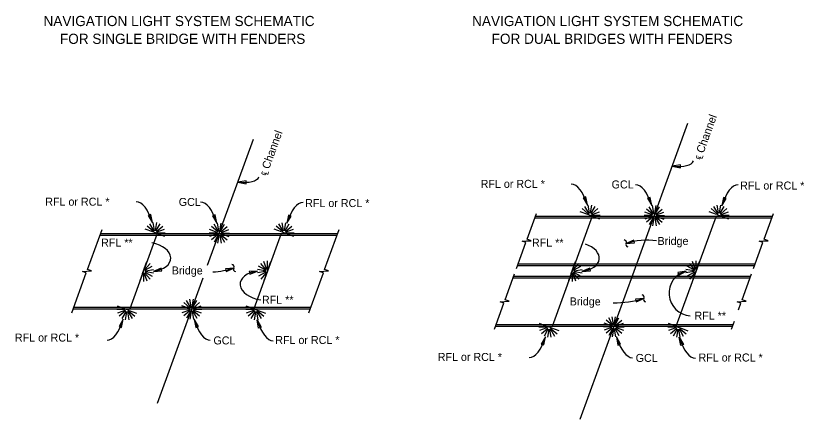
# Model space of a CAD drawing. Extents: x 84082 to 86787, y 72619 to 74101.
# Drawn here: x 84114 to 84859, y 73292 to 73673 of the extents above; entities that cross this region are included whole.
import ezdxf

# ---------------------------------------------------------------- set-up
doc = ezdxf.new("R2010")
doc.units = 0
for name, color, linetype in [('Dimension', 7, 'Continuous'), ('Miscellaneous', 7, 'Continuous'), ('NavLight', 7, 'Continuous'), ('SupstrConc', 7, 'Continuous'), ('TextStructures', 7, 'Continuous')]:
    doc.layers.add(name, color=color, linetype=linetype)

msp = doc.modelspace()

# ---------------------------------------------------------------- linework, layer by layer
at = {"layer": 'Dimension'}
for points in [[(84734.57, 73530.89), (84742.35, 73529.42), (84742.4, 73532.07)], [(84324.24, 73515.86), (84332.02, 73514.39), (84332.07, 73517.03)], [(84654.37, 73494.09), (84652.9, 73501.88), (84650.41, 73500.96)], [(84715.15, 73493.69), (84713.67, 73501.47), (84711.19, 73500.55)], [(84781.52, 73493.52), (84785.44, 73500.4), (84782.96, 73501.31)], [(84243.49, 73477.55), (84242.02, 73485.34), (84239.54, 73484.42)], [(84304.27, 73477.14), (84302.79, 73484.93), (84300.31, 73484.01)], [(84370.64, 73476.98), (84374.57, 73483.86), (84372.08, 73484.77)], [(84690.91, 73457.99), (84698.81, 73458.53), (84698.19, 73461.1)], [(84244.44, 73431.57), (84252.34, 73432.12), (84251.72, 73434.69)], [(84320.34, 73434.71), (84312.44, 73434.07), (84313.09, 73431.5)], [(84342.79, 73431.92), (84334.89, 73431.37), (84335.51, 73428.8)], [(84649.3, 73431.57), (84657.2, 73432.12), (84656.58, 73434.69)], [(84747.66, 73431.92), (84739.87, 73430.48), (84740.78, 73428)], [(84707.72, 73406.05), (84699.82, 73405.41), (84700.47, 73402.84)], [(84215.94, 73386.38), (84212.01, 73379.5), (84214.49, 73378.59)], [(84282.98, 73386.34), (84284.45, 73378.56), (84286.93, 73379.48)], [(84342.4, 73385.85), (84346.33, 73378.97), (84343.84, 73378.06)], [(84614.77, 73369.84), (84610.85, 73362.96), (84613.33, 73362.05)], [(84681.82, 73369.8), (84683.29, 73362.02), (84685.77, 73362.94)], [(84741.24, 73369.31), (84745.16, 73362.43), (84742.68, 73361.52)]]:
    msp.add_lwpolyline(points, close=True, dxfattribs=at)
for points in [[(84587.41, 73434.14), (84596.35, 73458.7), (84592.71, 73460.02), (84596.93, 73460.28), (84601.15, 73460.54), (84597.5, 73461.87), (84606.41, 73486.34)], [(84811.29, 73434.14), (84820.23, 73458.7), (84816.59, 73460.02), (84820.81, 73460.28), (84825.03, 73460.54), (84821.39, 73461.87), (84830.29, 73486.34)], [(84167.4, 73392.51), (84181.1, 73430.16), (84177.46, 73431.48), (84181.68, 73431.74), (84185.9, 73432), (84182.26, 73433.33), (84195.98, 73471.02)], [(84391.29, 73392.51), (84404.99, 73430.16), (84401.35, 73431.48), (84405.56, 73431.74), (84409.78, 73432), (84406.14, 73433.33), (84419.86, 73471.02)], [(84566.63, 73377.05), (84575.57, 73401.61), (84571.93, 73402.94), (84576.15, 73403.2), (84580.37, 73403.46), (84576.73, 73404.79), (84585.63, 73429.25)], [(84797.12, 73395.19), (84799.46, 73401.61), (84795.82, 73402.94), (84800.03, 73403.2), (84804.25, 73403.46), (84800.61, 73404.79), (84809.52, 73429.25)], [(84790.52, 73377.05), (84793.25, 73384.56)]]:
    msp.add_lwpolyline(points, dxfattribs=at)
for centre, radius, start, end in [((84688.95, 73459.02), 2.24, 331.78441, 83.51163), ((84692.89, 73456.9), 2.24, 151.78441, 263.51163), ((84710.59, 73395.97), 65.06, 81.92792, 107.60511), ((84292.44, 73528.24), 97.6, 274.88318, 286.60889), ((84318.37, 73435.83), 2.24, 330.78819, 82.51541), ((84322.28, 73433.65), 2.24, 150.78819, 262.51541), ((84753.19, 73411.03), 21.61, 104.83071, 265.42671), ((84705.76, 73407.17), 2.24, 330.78819, 82.51541), ((84679.82, 73499.58), 97.6, 269.35418, 286.60889), ((84709.66, 73404.99), 2.24, 150.78819, 262.51541)]:
    msp.add_arc(centre, radius, start, end, dxfattribs=at)
for centre, major_axis, ratio, start_param, end_param in [((84689.49, 73561.91), (-65, 26.05), 0.265294, 2.43766, 3.141592), ((84279.16, 73546.88), (-65, 26.05), 0.265294, 2.43766, 3.141592), ((84640.04, 73456.55), (0.91, -57.27), 0.343516, 2.28027, 3.141592), ((84700.81, 73456.14), (0.91, -57.27), 0.343516, 2.28027, 3.141592), ((84795.85, 73455.98), (-0.91, -57.27), 0.343516, 3.141594, 4.002916), ((84229.16, 73440.01), (0.91, -57.27), 0.343516, 2.28027, 3.141592), ((84289.93, 73439.6), (0.91, -57.27), 0.343516, 2.28027, 3.141592), ((84384.97, 73439.44), (-0.91, -57.27), 0.343516, 3.141594, 4.002916), ((84237.96, 73445.24), (-22.85, 1.95), 0.604289, 1.909459, 4.535813), ((84642.82, 73445.24), (-22.85, 1.95), 0.604289, 1.909459, 4.325024), ((84349.27, 73418.25), (22.85, -1.95), 0.604289, 1.909459, 4.612762), ((84201.6, 73423.92), (0.91, 57.27), 0.343516, 3.141594, 4.002916), ((84297.31, 73423.88), (-0.91, 57.27), 0.343516, 2.28027, 3.141592), ((84356.73, 73423.39), (-0.91, 57.27), 0.343516, 2.28027, 3.141592), ((84600.44, 73407.38), (0.91, 57.27), 0.343516, 3.141594, 4.002916), ((84696.15, 73407.34), (-0.91, 57.27), 0.343516, 2.28027, 3.141592), ((84755.57, 73406.85), (-0.91, 57.27), 0.343516, 2.28027, 3.141592)]:
    msp.add_ellipse(centre, major_axis=major_axis, ratio=ratio, start_param=start_param, end_param=end_param, dxfattribs=at)
at = {"layer": 'Miscellaneous'}
for p, q in [((84698.48, 73431.74), (84749.36, 73571.54)), ((84295.68, 73437.39), (84339.03, 73556.51)), ((84658.91, 73483.83), (84620.99, 73379.66)), ((84775.97, 73483.83), (84738.05, 73379.66)), ((84248.03, 73467.28), (84222.16, 73396.2)), ((84365.09, 73467.28), (84339.22, 73396.2)), ((84647.6, 73291.94), (84698.48, 73431.74)), ((84248.21, 73306.98), (84291.36, 73425.53))]:
    msp.add_line(p, q, dxfattribs=at)
at = {"layer": 'NavLight'}
for p, q in [((84655.67, 73486.56), (84651.97, 73492.97)), ((84656.41, 73486.83), (84655.12, 73494.12)), ((84657.19, 73486.83), (84658.47, 73494.12)), ((84657.92, 73486.56), (84661.63, 73492.97)), ((84716.45, 73486.15), (84712.75, 73492.56)), ((84717.18, 73486.42), (84715.9, 73493.71)), ((84717.97, 73486.42), (84719.25, 73493.71)), ((84718.7, 73486.15), (84722.4, 73492.56)), ((84777.49, 73486.56), (84773.79, 73492.97)), ((84778.25, 73486.81), (84776.97, 73494.1)), ((84779.03, 73486.81), (84780.32, 73494.1)), ((84779.77, 73486.54), (84783.47, 73492.95)), ((84654.68, 73485.38), (84647.73, 73487.91)), ((84655.07, 73486.06), (84649.4, 73490.81)), ((84658.91, 73483.83), (84654.68, 73485.38)), ((84658.52, 73486.06), (84664.19, 73490.81)), ((84658.94, 73483.81), (84665.89, 73481.28)), ((84658.95, 73485.38), (84665.9, 73487.91)), ((84659.08, 73484.59), (84666.48, 73484.59)), ((84715.32, 73484.2), (84707.92, 73484.2)), ((84715.46, 73484.97), (84708.5, 73487.5)), ((84715.46, 73483.43), (84708.5, 73480.9)), ((84715.85, 73485.65), (84710.18, 73490.4)), ((84719.33, 73485.66), (84725, 73490.41)), ((84719.72, 73484.97), (84726.68, 73487.5)), ((84719.72, 73483.43), (84726.68, 73480.9)), ((84719.86, 73484.22), (84727.26, 73484.22)), ((84776.49, 73485.36), (84769.54, 73487.89)), ((84776.88, 73486.05), (84771.21, 73490.81)), ((84776.52, 73485.35), (84780.76, 73483.83)), ((84780.37, 73486.04), (84786.04, 73490.8)), ((84780.76, 73485.36), (84787.71, 73487.9)), ((84780.76, 73483.83), (84787.71, 73481.29)), ((84780.89, 73484.6), (84788.29, 73484.6)), ((84244.79, 73470.02), (84241.09, 73476.43)), ((84245.53, 73470.28), (84244.24, 73477.57)), ((84246.31, 73470.28), (84247.6, 73477.57)), ((84247.04, 73470.02), (84250.75, 73476.43)), ((84305.57, 73469.61), (84301.87, 73476.02)), ((84306.3, 73469.87), (84305.02, 73477.16)), ((84307.09, 73469.87), (84308.37, 73477.16)), ((84307.82, 73469.61), (84311.52, 73476.02)), ((84366.61, 73470.02), (84362.91, 73476.43)), ((84367.37, 73470.27), (84366.09, 73477.56)), ((84368.15, 73470.27), (84369.44, 73477.56)), ((84368.89, 73470), (84372.59, 73476.41)), ((84715.85, 73482.75), (84710.18, 73478)), ((84716.45, 73482.25), (84712.75, 73475.84)), ((84717.18, 73481.98), (84715.9, 73474.69)), ((84717.97, 73481.98), (84719.25, 73474.69)), ((84718.7, 73482.25), (84722.4, 73475.84)), ((84719.33, 73482.75), (84725, 73477.99)), ((84243.81, 73468.84), (84236.85, 73471.37)), ((84244.2, 73469.51), (84238.53, 73474.27)), ((84248.03, 73467.28), (84243.81, 73468.84)), ((84247.64, 73469.51), (84253.31, 73474.27)), ((84248.07, 73468.83), (84255.03, 73471.37)), ((84304.58, 73468.43), (84297.62, 73470.96)), ((84304.97, 73469.11), (84299.3, 73473.86)), ((84308.45, 73469.11), (84314.12, 73473.87)), ((84308.85, 73468.42), (84315.8, 73470.96)), ((84365.61, 73468.82), (84358.66, 73471.35)), ((84366, 73469.51), (84360.33, 73474.27)), ((84365.64, 73468.81), (84369.88, 73467.28)), ((84369.49, 73469.5), (84375.16, 73474.26)), ((84369.88, 73468.82), (84376.83, 73471.35)), ((84248.06, 73467.27), (84255.01, 73464.74)), ((84248.2, 73468.05), (84255.6, 73468.05)), ((84304.44, 73467.66), (84297.04, 73467.66)), ((84304.58, 73466.89), (84297.62, 73464.36)), ((84304.97, 73466.21), (84299.3, 73461.45)), ((84305.57, 73465.71), (84301.87, 73459.3)), ((84306.3, 73465.44), (84305.02, 73458.15)), ((84307.09, 73465.44), (84308.37, 73458.15)), ((84307.82, 73465.71), (84311.52, 73459.3)), ((84308.45, 73466.2), (84314.12, 73461.45)), ((84308.85, 73466.89), (84315.8, 73464.36)), ((84308.98, 73467.67), (84316.38, 73467.67)), ((84369.88, 73467.28), (84376.83, 73464.75)), ((84370.01, 73468.05), (84377.42, 73468.05)), ((84235.86, 73433.86), (84238.39, 73440.81)), ((84236.54, 73433.47), (84241.3, 73439.14)), ((84350.71, 73433.47), (84345.95, 73439.14)), ((84351.38, 73433.86), (84348.85, 73440.81)), ((84352.15, 73433.99), (84352.15, 73441.39)), ((84352.92, 73433.86), (84355.45, 73440.81)), ((84640.72, 73433.86), (84643.25, 73440.81)), ((84641.4, 73433.47), (84646.16, 73439.14)), ((84755.56, 73433.47), (84750.81, 73439.14)), ((84756.24, 73433.86), (84753.71, 73440.81)), ((84757.01, 73433.99), (84757.01, 73441.39)), ((84757.78, 73433.86), (84760.31, 73440.81)), ((84234.31, 73429.63), (84235.86, 73433.86)), ((84237.04, 73432.87), (84243.45, 73436.57)), ((84237.31, 73432.13), (84244.6, 73433.42)), ((84237.31, 73431.35), (84244.6, 73430.07)), ((84349.94, 73432.13), (84342.65, 73433.42)), ((84349.94, 73431.35), (84342.65, 73430.07)), ((84350.2, 73432.87), (84343.79, 73436.57)), ((84351.4, 73429.62), (84352.92, 73433.86)), ((84639.17, 73429.63), (84640.72, 73433.86)), ((84641.9, 73432.87), (84648.31, 73436.57)), ((84642.17, 73432.13), (84649.46, 73433.42)), ((84642.17, 73431.35), (84649.46, 73430.07)), ((84754.79, 73432.13), (84747.5, 73433.42)), ((84754.79, 73431.35), (84747.5, 73430.07)), ((84755.06, 73432.87), (84748.65, 73436.57)), ((84756.26, 73429.62), (84757.78, 73433.86)), ((84234.3, 73429.6), (84231.77, 73422.65)), ((84235.08, 73429.46), (84235.08, 73422.06)), ((84235.86, 73429.59), (84238.39, 73422.64)), ((84236.54, 73430.02), (84241.3, 73424.35)), ((84237.04, 73430.62), (84243.45, 73426.92)), ((84350.18, 73430.59), (84343.77, 73426.89)), ((84350.7, 73429.98), (84345.94, 73424.31)), ((84351.39, 73429.59), (84348.85, 73422.64)), ((84639.16, 73429.6), (84636.62, 73422.65)), ((84639.94, 73429.46), (84639.94, 73422.06)), ((84640.72, 73429.59), (84643.25, 73422.64)), ((84641.4, 73430.02), (84646.16, 73424.35)), ((84641.9, 73430.62), (84648.31, 73426.92)), ((84755.04, 73430.59), (84748.63, 73426.89)), ((84755.56, 73429.98), (84750.8, 73424.31)), ((84756.24, 73429.59), (84753.71, 73422.64)), ((84278.83, 73397.27), (84273.16, 73402.03)), ((84279.42, 73397.77), (84275.72, 73404.18)), ((84280.16, 73398.04), (84278.87, 73405.33)), ((84280.94, 73398.04), (84282.23, 73405.33)), ((84281.68, 73397.77), (84285.38, 73404.18)), ((84282.31, 73397.28), (84287.98, 73402.04)), ((84217.23, 73395.43), (84209.83, 73395.43)), ((84217.37, 73396.2), (84210.41, 73398.73)), ((84217.37, 73394.66), (84210.41, 73392.13)), ((84221.6, 73394.68), (84217.37, 73396.2)), ((84221.63, 73394.66), (84228.59, 73392.13)), ((84278.3, 73395.83), (84270.9, 73395.83)), ((84278.44, 73396.6), (84271.48, 73399.13)), ((84278.44, 73395.06), (84271.48, 73392.52)), ((84278.83, 73394.38), (84273.16, 73389.62)), ((84282.31, 73394.37), (84287.98, 73389.61)), ((84282.7, 73396.59), (84289.66, 73399.12)), ((84282.7, 73395.06), (84289.66, 73392.53)), ((84282.83, 73395.84), (84290.23, 73395.84)), ((84339.04, 73395.43), (84331.64, 73395.43)), ((84339.18, 73394.65), (84332.22, 73392.12)), ((84339.19, 73396.21), (84332.23, 73398.74)), ((84339.22, 73396.2), (84343.44, 73394.65)), ((84343.44, 73394.65), (84350.4, 73392.12)), ((84217.76, 73393.98), (84212.09, 73389.23)), ((84218.36, 73393.48), (84214.66, 73387.07)), ((84219.09, 73393.21), (84217.81, 73385.92)), ((84219.87, 73393.21), (84221.16, 73385.92)), ((84220.64, 73393.46), (84224.34, 73387.05)), ((84221.24, 73393.98), (84226.91, 73389.22)), ((84279.42, 73393.88), (84275.72, 73387.47)), ((84280.16, 73393.61), (84278.87, 73386.32)), ((84280.94, 73393.61), (84282.23, 73386.32)), ((84281.68, 73393.88), (84285.38, 73387.47)), ((84339.6, 73393.97), (84333.93, 73389.21)), ((84340.2, 73393.47), (84336.5, 73387.06)), ((84340.93, 73393.2), (84339.65, 73385.91)), ((84341.72, 73393.2), (84343, 73385.91)), ((84342.45, 73393.47), (84346.15, 73387.06)), ((84343.05, 73393.97), (84348.72, 73389.21)), ((84678.26, 73381.23), (84674.56, 73387.64)), ((84679, 73381.5), (84677.71, 73388.79)), ((84679.78, 73381.5), (84681.06, 73388.79)), ((84680.51, 73381.23), (84684.21, 73387.64)), ((84616.21, 73379.66), (84609.25, 73382.19)), ((84620.44, 73378.13), (84616.21, 73379.66)), ((84677.14, 73379.28), (84669.74, 73379.28)), ((84677.27, 73380.05), (84670.32, 73382.58)), ((84677.66, 73380.73), (84671.99, 73385.49)), ((84681.15, 73380.74), (84686.82, 73385.5)), ((84681.54, 73380.05), (84688.49, 73382.58)), ((84681.67, 73379.3), (84689.07, 73379.3)), ((84738.02, 73379.67), (84731.07, 73382.2)), ((84738.05, 73379.66), (84742.28, 73378.1)), ((84616.07, 73378.89), (84608.67, 73378.89)), ((84616.21, 73378.12), (84609.25, 73375.59)), ((84616.6, 73377.44), (84610.93, 73372.68)), ((84617.19, 73376.94), (84613.49, 73370.53)), ((84617.93, 73376.67), (84616.64, 73369.38)), ((84618.71, 73376.67), (84620, 73369.38)), ((84619.47, 73376.92), (84623.18, 73370.51)), ((84620.08, 73377.43), (84625.75, 73372.68)), ((84620.47, 73378.12), (84627.43, 73375.59)), ((84677.27, 73378.51), (84670.32, 73375.98)), ((84677.66, 73377.84), (84671.99, 73373.08)), ((84678.26, 73377.33), (84674.56, 73370.92)), ((84679, 73377.07), (84677.71, 73369.78)), ((84679.78, 73377.07), (84681.06, 73369.78)), ((84680.51, 73377.33), (84684.21, 73370.92)), ((84681.15, 73377.83), (84686.82, 73373.07)), ((84681.54, 73378.52), (84688.49, 73375.99)), ((84737.88, 73378.89), (84730.48, 73378.89)), ((84738.01, 73378.11), (84731.06, 73375.58)), ((84738.44, 73377.43), (84732.77, 73372.67)), ((84739.04, 73376.93), (84735.34, 73370.52)), ((84739.77, 73376.66), (84738.49, 73369.37)), ((84740.55, 73376.66), (84741.84, 73369.37)), ((84741.29, 73376.93), (84744.99, 73370.52)), ((84741.89, 73377.43), (84747.56, 73372.67)), ((84742.28, 73378.1), (84749.23, 73375.57))]:
    msp.add_line(p, q, dxfattribs=at)
for centre in [(84717.57, 73484.2), (84306.7, 73467.66), (84280.55, 73395.83), (84679.39, 73379.28)]:
    msp.add_circle(centre, 2.25, dxfattribs=at)
for centre, start, end in [((84656.8, 73484.61), 339.6086, 160), ((84778.64, 73484.6), 340, 160.3914), ((84245.92, 73468.07), 339.6086, 160), ((84367.76, 73468.05), 340, 160.3914), ((84235.09, 73431.74), 249.6086, 70), ((84352.15, 73431.74), 70, 250.3914), ((84639.95, 73431.74), 249.6086, 70), ((84757.01, 73431.74), 70, 250.3914), ((84219.48, 73395.43), 160, 340.3914), ((84341.33, 73395.42), 159.6086, 340), ((84618.32, 73378.89), 160, 340.3914), ((84740.16, 73378.87), 159.6086, 340)]:
    msp.add_arc(centre, 2.25, start, end, dxfattribs=at)
at = {"layer": 'SupstrConc'}
for p, q in [((84605.5, 73483.83), (84829.38, 73483.83)), ((84604.93, 73482.28), (84828.82, 73482.28)), ((84194.06, 73465.74), (84417.94, 73465.74)), ((84194.62, 73467.28), (84418.5, 73467.28)), ((84812.24, 73436.74), (84588.36, 73436.74)), ((84812.8, 73438.28), (84588.92, 73438.28)), ((84808.04, 73425.2), (84584.16, 73425.2)), ((84808.6, 73426.74), (84584.72, 73426.74)), ((84168.74, 73396.2), (84392.63, 73396.2)), ((84169.31, 73397.74), (84393.19, 73397.74)), ((84791.47, 73379.66), (84567.58, 73379.66)), ((84792.03, 73381.2), (84568.14, 73381.2))]:
    msp.add_line(p, q, dxfattribs=at)

# ---------------------------------------------------------------- texts
at = {"layer": 'Dimension'}
for s, p in [('NAVIGATION LIGHT SYSTEM SCHEMATIC', (84140.65, 73663.21)), ('NAVIGATION LIGHT SYSTEM SCHEMATIC', (84545.51, 73663.21)), ('FOR SINGLE BRIDGE WITH FENDERS', (84156.17, 73646.41)), ('FOR DUAL BRIDGES WITH FENDERS', (84563.95, 73646.41))]:
    msp.add_text(s, height=9.6, dxfattribs=at).set_placement(p)
at = {"layer": 'TextStructures'}
for p in [(84761.72, 73536.15), (84351.39, 73521.11)]:
    msp.add_text('℄ Channel', height=7.56, rotation=70, dxfattribs=at).set_placement(p)
for s, p in [('RFL or RCL *', (84553.58, 73510.43)), ('GCL', (84677.3, 73509.88)), ('RFL or RCL *', (84798.7, 73508.83)), ('RFL or RCL *', (84142.33, 73493.6)), ('GCL', (84268.44, 73493.34)), ('RFL or RCL *', (84387.82, 73492.29)), ('RFL **', (84195.05, 73454.95)), ('RFL **', (84602.06, 73454.95)), ('Bridge ', (84720.65, 73456.5)), ('Bridge ', (84261.8, 73428.66)), ('RFL **', (84347.02, 73400.98)), ('Bridge ', (84637.7, 73399.42)), ('RFL **', (84755.53, 73385.98)), ('RFL or RCL *', (84113.65, 73365.25)), ('GCL', (84301.19, 73362.58)), ('RFL or RCL *', (84359.58, 73362.98)), ('RFL or RCL *', (84513.05, 73346.97)), ('GCL', (84700.03, 73346.04)), ('RFL or RCL *', (84759.35, 73346.44))]:
    msp.add_text(s, height=7.56, dxfattribs=at).set_placement(p)

doc.saveas('drawing.dxf')
